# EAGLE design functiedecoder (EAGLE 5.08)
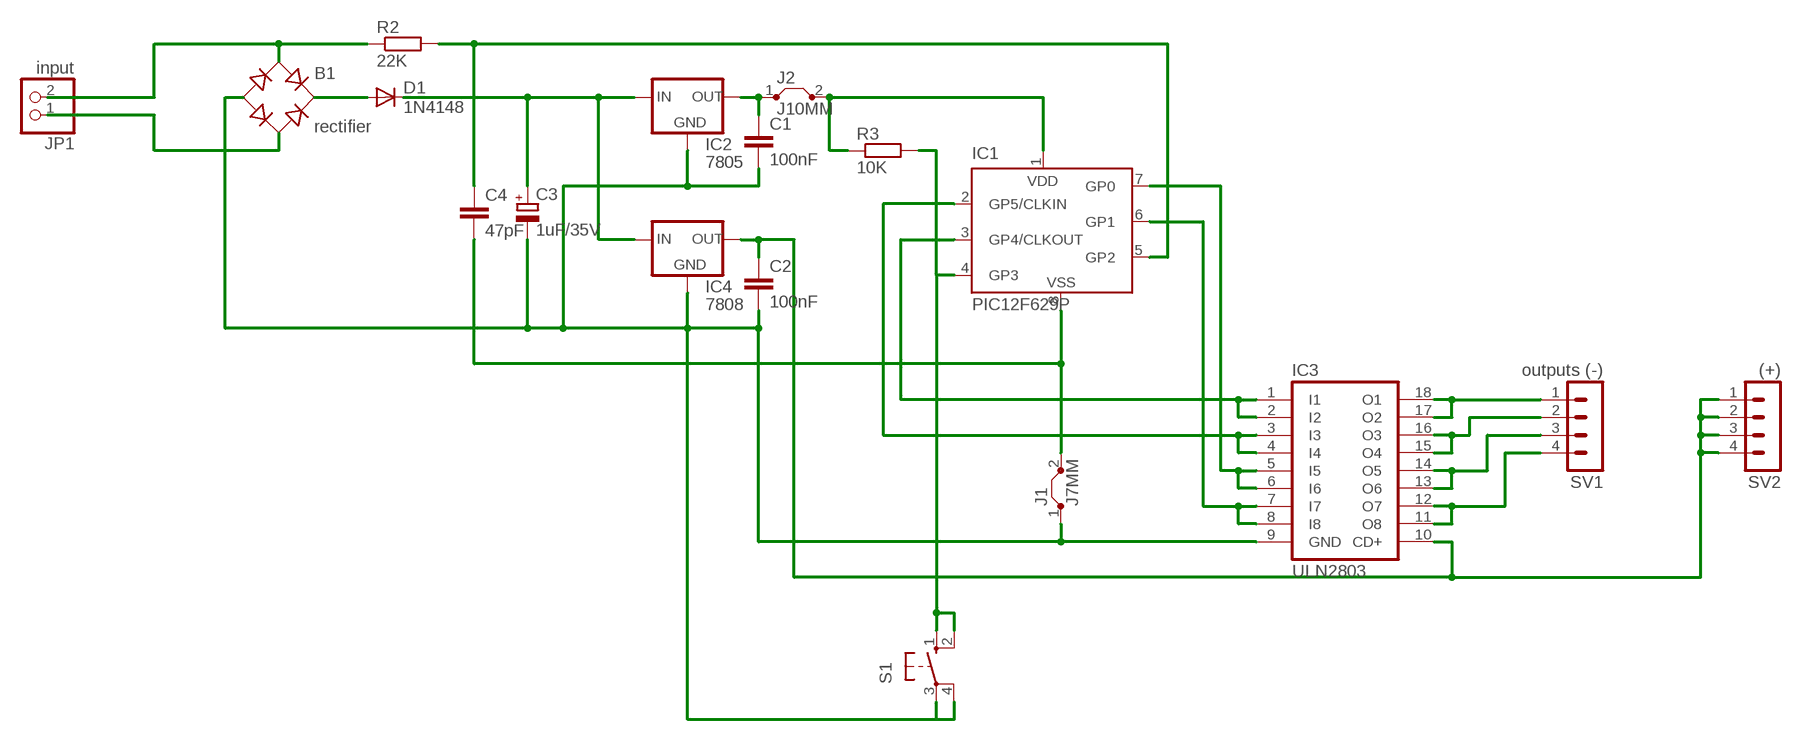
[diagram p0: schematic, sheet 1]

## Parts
B1  rectifier  RB1A  [RB1A]
C1  100nF  C-EU050-025X075  [C050-025X075]
C2  100nF  C-EU050-025X075  [C050-025X075]
C3  1uF/35V  CPOL-EUE2.5-6  [E2,5-6]
C4  47pF  C-EU050-025X075  [C050-025X075]
D1  1N4148  1N4148DO35-7  [DO35-7]
IC1  PIC12F629P  [DIL8]
IC2  7805  78XXS  [78XXS]
IC3  ULN2803  ULN2803A  [DIL18]
IC4  7808  78XXS  [78XXS]
J1  J7MM  [07]
J2  J10MM  [10]
JP1  input  PINHD-1X2  [1X02]
R2  22K  R-EU_0207/10  [0207/10]
R3  10K  R-EU_0207/10  [0207/10]
S1  10-XX  [B3F-10XX]
SV1  outputs (-)  MA04-1  [MA04-1]
SV2  (+)  MA04-1  [MA04-1]

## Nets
N$1: B1.AC1 JP1.2 R2.1
N$2: B1.AC2 JP1.1
N$3: B1.+ D1.A
N$4: IC1.7(GP0) IC3.5(I5) IC3.6(I6)
N$5: C3.+ D1.C IC2.IN IC4.IN
N$6: IC1.3(GP4/CLKOUT) IC3.1(I1) IC3.2(I2)
N$7: IC1.1(VDD) J2.2 R3.1
N$8: C2.1 IC3.10(CD+) IC4.OUT SV2.1 SV2.2 SV2.3 SV2.4
N$9: IC1.2(GP5/CLKIN) IC3.3(I3) IC3.4(I4)
N$10: C4.2 IC1.8(VSS) J1.2
N$11: IC1.6(GP1) IC3.7(I7) IC3.8(I8)
N$12: C4.1 IC1.5(GP2) R2.2
N$13: IC3.11(O8) IC3.12(O7) SV1.4
N$14: IC3.13(O6) IC3.14(O5) SV1.3
N$15: IC3.15(O4) IC3.16(O3) SV1.2
N$16: IC3.17(O2) IC3.18(O1) SV1.1
N$17: IC1.4(GP3) R3.2 S1.1(S) S1.2(S1)
N$18: C1.1 IC2.OUT J2.1
N$19: B1.- C1.2 C2.2 C3.- IC2.GND IC3.9(GND) IC4.GND J1.1 S1.3(P) S1.4(P1)

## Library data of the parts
B1 = rectifier:RB1A: RECTIFIER 1 A
C1 C2 C4 = rcl:C-EU: CAPACITOR, European symbol
C3 = rcl:CPOL-EU: POLARIZED CAPACITOR, European symbol
D1 = diode:1N4148: DIODE
IC1 = microchip:PIC12F6*: Data Sheet 8-Pin FLASH-Based 8-Bit CMOS Microcontrollers Source: http://www.microchip.com .. 41190c.pdf
IC2 IC4 = v-reg:78XXS: VOLTAGE REGULATOR
IC3 = uln-udn:ULN2803A: DRIVER ARRAY
J1 J2 = jumper:J: Bridge
JP1 = pinhead:PINHD-1X2: PIN HEADER
R2 R3 = rcl:R-EU_: RESISTOR, European symbol
S1 = switch-omron:10-XX: OMRON SWITCH
SV1 SV2 = con-lstb:MA04-1: PIN HEADER

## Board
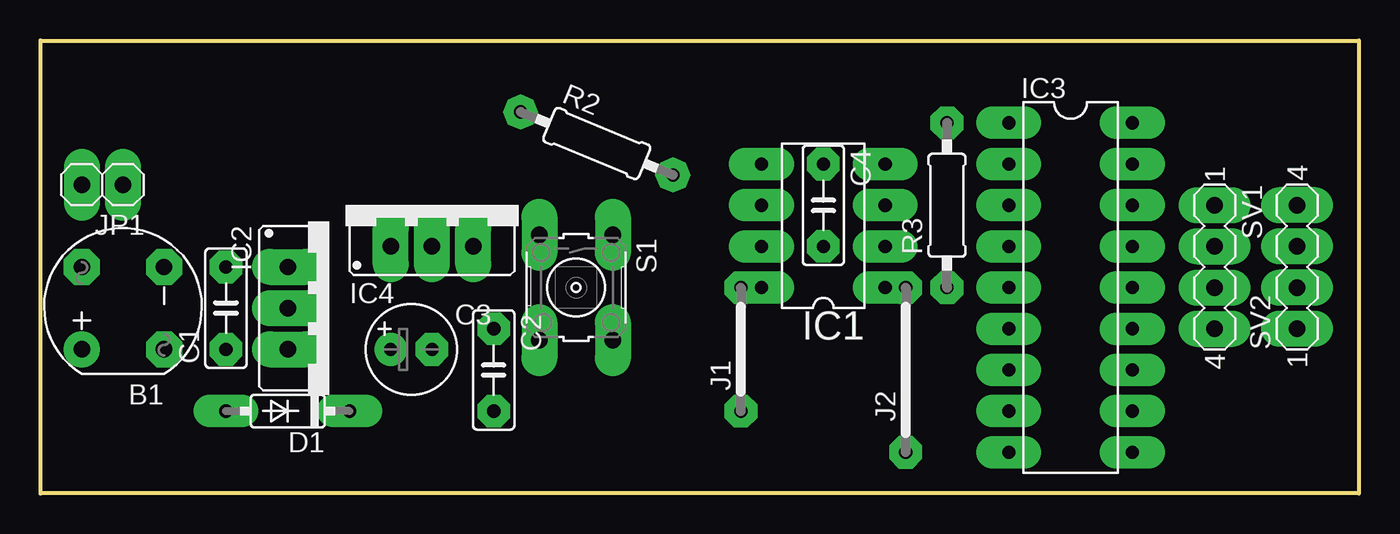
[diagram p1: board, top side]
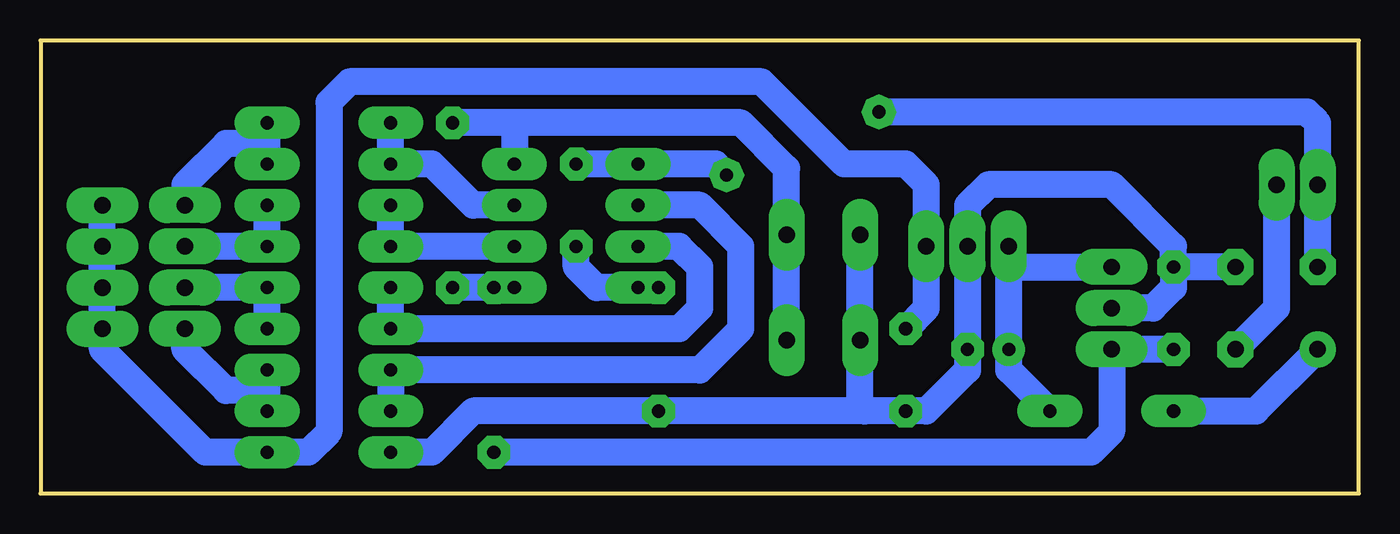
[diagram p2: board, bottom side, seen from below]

Size 81.28 x 27.94 mm. Coordinates in mm from the lower left corner, seen from the top.
Outline: 0,0 0,27.94 81.28,27.94 81.28,0 0,0
Copper layers (1*16): Top 1mm / dielectric 1.5mm / Bottom 1mm
Design rules "DRC settings middle": minimum track width 1.2mm, minimum drill 24mil, track to track 0.4mm, track to pad 0.4mm, pad to pad 0.4mm, via to via 0.4mm, smd to smd 8mil, copper to edge 0.5mm, drill to drill 0.5mm, minimum pad ring 0.6mm, minimum via ring 1mm, stop-mask expansion 4mil, vias tented up to drill 0mil, thermal gap 10mil

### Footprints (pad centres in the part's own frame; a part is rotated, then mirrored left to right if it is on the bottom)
RB1A = drill 1.016 round: + -2.54,2.54 | drill 1.016 octagon: - 2.54,-2.54; AC1 2.54,2.54; AC2 -2.54,-2.54
C050-025X075 = drill 0.813 octagon: 1 -2.54,0; 2 2.54,0
E2,5-6 = drill 0.813 pad 1.6 round: + -1.27,0 | drill 0.813 pad 1.6 octagon: - 1.27,0
DO35-7 = drill 0.813 long: A 3.81,0; C -3.81,0
DIL8 = drill 0.813 long: 1 -3.81,-3.81; 2 -1.27,-3.81; 3 1.27,-3.81; 4 3.81,-3.81; 5 3.81,3.81; 6 1.27,3.81; 7 -1.27,3.81; 8 -3.81,3.81
78XXS = drill 1.016 long: GND 0,-2.54; IN -2.54,-2.54; OUT 2.54,-2.54
DIL18 = drill 0.813 long: 1 -10.16,-3.81; 2 -7.62,-3.81; 3 -5.08,-3.81; 4 -2.54,-3.81; 5 0,-3.81; 6 2.54,-3.81; 7 5.08,-3.81; 8 7.62,-3.81; 9 10.16,-3.81; 10 10.16,3.81; 11 7.62,3.81; 12 5.08,3.81; 13 2.54,3.81; 14 0,3.81; 15 -2.54,3.81; 16 -5.08,3.81; 17 -7.62,3.81; 18 -10.16,3.81
07 = drill 0.813 pad 1.6 octagon: 1 -3.81,0; 2 3.81,0
10 = drill 0.813 pad 1.6 octagon: 1 -5.08,0; 2 5.08,0
1X02 = drill 1.016 long: 1 -1.27,0; 2 1.27,0
0207/10 = drill 0.813 octagon: 1 -5.08,0; 2 5.08,0
B3F-10XX = drill 1.016 long: 1 -3.251,2.261; 2 3.251,2.261; 3 -3.251,-2.261; 4 3.251,-2.261
MA04-1 = drill 1.016 long: 1 -3.81,0; 2 -1.27,0; 3 1.27,0; 4 3.81,0

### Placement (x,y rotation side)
B1  5.08,11.43 90 top
C1  11.43,11.43 90 top
C2  27.94,7.62 270 top
C3  22.86,8.89 0 top
C4  48.26,17.78 270 top
D1  15.24,5.08 180 top
IC1  48.26,16.51 90 top
IC2  17.78,11.43 270 top
IC3  63.5,12.7 270 top
IC4  24.13,17.78 0 top
J1  43.18,8.89 90 top
J2  53.34,7.62 90 top
JP1  3.81,19.05 180 top
R2  34.29,21.59 337.5 top
R3  55.88,17.78 90 top
S1  33.02,12.7 270 top
SV1  72.39,13.97 270 top
SV2  77.47,13.97 90 top

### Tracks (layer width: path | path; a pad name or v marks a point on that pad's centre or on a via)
N$1
  Bottom 1.676: R2.1 3.21,23.53 2.54,22.86 JP1.2 B1.AC1
N$2
  Bottom 1.676: B1.AC2 5.08,11.43 JP1.1
N$3
  Bottom 1.676: D1.A 6.35,5.08 B1.+
N$4
  Bottom 1.676: IC3.5 IC3.6 41.91,10.16 40.64,11.43 40.64,13.97 41.91,15.24 IC1.7
N$5
  Bottom 1.676: 21.59,13.97 IC4.IN | 21.59,13.97 IC2.IN | 21.59,13.97 C3.+ 21.59,7.62 D1.C
N$6
  Bottom 1.676: IC3.1 IC3.2 57.15,20.32 54.61,17.78 IC1.3
N$7
  Bottom 1.676: R3.1 J2.2 IC1.1
N$8
  Bottom 1.676: SV2.4 SV2.3 SV2.2 SV2.1 77.47,8.89 71.12,2.54 IC3.10 64.77,2.54 63.5,3.81 63.5,24.13 62.23,25.4 36.83,25.4 31.75,20.32 27.94,20.32 26.67,19.05 IC4.OUT | C2.1 26.67,11.43 IC4.OUT | IC4.OUT 26.67,16.51
N$9
  Bottom 1.676: IC3.3 IC3.4 IC1.2
N$10
  Bottom 1.676: J1.2 IC1.8 46.99,12.7 48.26,13.97 C4.2
N$11
  Bottom 1.676: IC3.8 IC3.7 40.64,7.62 38.1,10.16 38.1,15.24 40.64,17.78 IC1.6
N$12
  Bottom 1.676: C4.1 IC1.5 39.66,20.32 R2.2
N$13
  Bottom 1.676: IC3.11 67.31,6.35 | 67.31,6.35 IC3.12 | SV1.4 72.39,8.89 69.85,6.35 67.31,6.35
N$14
  Bottom 1.676: SV1.3 IC3.14 IC3.13
N$15
  Bottom 1.676: SV1.2 IC3.15 IC3.16
N$16
  Bottom 1.676: IC3.17 67.31,21.59 | 67.31,21.59 IC3.18 | SV1.1 72.39,19.05 69.85,21.59 67.31,21.59
N$17
  Bottom 1.676: 52.07,22.86 R3.2 | 52.07,22.86 IC1.4 | S1.2 S1.1 35.28,20.04 38.1,22.86 52.07,22.86
N$18
  Bottom 1.676: C1.1 IC2.OUT 15.24,3.81 16.51,2.54 J2.1
N$19
  Bottom 1.676: IC3.9 57.15,2.54 54.61,5.08 J1.1 30.48,5.08 | C1.2 11.43,15.24 15.24,19.05 22.86,19.05 24.13,17.78 IC4.GND C3.- 24.13,7.62 26.67,5.08 C2.2 30.48,5.08 | IC2.GND 12.7,11.43 11.43,12.7 C1.2 | S1.3 S1.4 30.76,5.36 30.48,5.08 | B1.- C1.2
